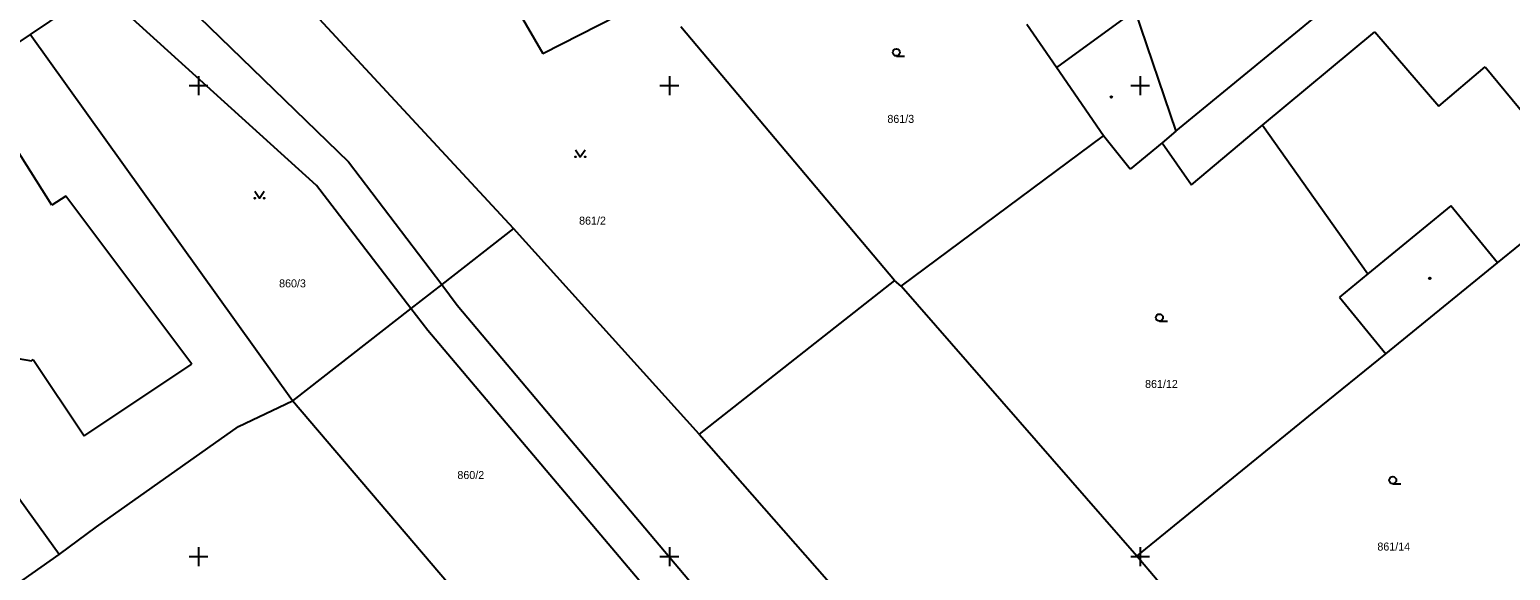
# Model space of a CAD drawing. Extents: x -711081 to -709338, y -1025122 to -1024092.
# Drawn here: x -710884 to -710805.3, y -1025025.7 to -1024997 of the extents above; entities that cross this region are included whole.
import ezdxf

# ---------------------------------------------------------------- set-up
doc = ezdxf.new("R2010")
doc.units = 0
for name, color, linetype in [('Z_hektometricka_sit', 7, 'Continuous'), ('Z_katastr_cisla_pozemkova', 7, 'Continuous'), ('Z_katastr_hranice', 7, 'Continuous'), ('Z_katastr_vnitrni_kresba', 7, 'Continuous'), ('Z_katastr_znacky_budov', 7, 'Continuous'), ('Z_katastr_znacky_kultur', 7, 'Continuous')]:
    doc.layers.add(name, color=color, linetype=linetype)

msp = doc.modelspace()

# ---------------------------------------------------------------- linework, layer by layer
at = {"layer": 'Z_hektometricka_sit'}
for p, q in [((-710875.5, -1025000), (-710874.5, -1025000)), ((-710875, -1024999.5), (-710875, -1025000.5)), ((-710850.5, -1025000), (-710849.5, -1025000)), ((-710850, -1024999.5), (-710850, -1025000.5)), ((-710825.5, -1025000), (-710824.5, -1025000)), ((-710825, -1024999.5), (-710825, -1025000.5)), ((-710875.5, -1025025), (-710874.5, -1025025)), ((-710875, -1025024.5), (-710875, -1025025.5)), ((-710850.5, -1025025), (-710849.5, -1025025)), ((-710850, -1025024.5), (-710850, -1025025.5)), ((-710825.5, -1025025), (-710824.5, -1025025)), ((-710825, -1025024.5), (-710825, -1025025.5))]:
    msp.add_line(p, q, dxfattribs=at)
at = {"layer": 'Z_katastr_hranice'}
for p, q in [((-710864.81, -1024984.43), (-710856.72, -1024998.29)), ((-710858.27, -1025007.58), (-710874.03, -1024990.6)), ((-710879.89, -1024994.55), (-710883.95, -1024997.28)), ((-710856.72, -1024998.29), (-710850.8, -1024995.28)), ((-710825.28, -1024996.01), (-710823.1, -1025002.42)), ((-710838.05, -1025010.34), (-710849.39, -1024996.89)), ((-710829.45, -1024999.04), (-710831.02, -1024996.76)), ((-710823.1, -1025002.42), (-710815.65, -1024996.32)), ((-710883.95, -1024997.28), (-710887.15, -1024999.45)), ((-710870.02, -1025016.74), (-710883.95, -1024997.28)), ((-710826.95, -1025002.67), (-710829.45, -1024999.04)), ((-710882.8, -1025006.35), (-710887.15, -1024999.45)), ((-710823.1, -1025002.42), (-710823.84, -1025003.03)), ((-710822.28, -1025005.26), (-710818.5, -1025002.1)), ((-710818.5, -1025002.1), (-710812.92, -1025010)), ((-710837.7, -1025010.65), (-710826.95, -1025002.67)), ((-710825.54, -1025004.43), (-710826.95, -1025002.67)), ((-710823.84, -1025003.03), (-710825.54, -1025004.43)), ((-710823.84, -1025003.03), (-710822.28, -1025005.26)), ((-710882.04, -1025005.87), (-710882.8, -1025006.35)), ((-710875.35, -1025014.79), (-710882.04, -1025005.87)), ((-710858.27, -1025007.58), (-710862.09, -1025010.56)), ((-710848.42, -1025018.5), (-710858.27, -1025007.58)), ((-710806.03, -1025009.41), (-710804.81, -1025008.42)), ((-710811.96, -1025014.24), (-710806.03, -1025009.41)), ((-710812.92, -1025010), (-710814.41, -1025011.23)), ((-710862.09, -1025010.56), (-710863.72, -1025011.83)), ((-710838.05, -1025010.34), (-710848.42, -1025018.5)), ((-710837.7, -1025010.65), (-710838.05, -1025010.34)), ((-710825.17, -1025024.98), (-710837.7, -1025010.65)), ((-710863.72, -1025011.83), (-710870.02, -1025016.74)), ((-710814.41, -1025011.23), (-710811.96, -1025014.24)), ((-710815.76, -1025017.32), (-710811.96, -1025014.24)), ((-710885.39, -1025014.35), (-710883.88, -1025014.61)), ((-710883.88, -1025014.61), (-710883.78, -1025014.53)), ((-710883.78, -1025014.53), (-710881.08, -1025018.59)), ((-710881.08, -1025018.59), (-710875.35, -1025014.79)), ((-710872.88, -1025018.09), (-710870.02, -1025016.74)), ((-710846.935, -1025043.764), (-710870.02, -1025016.74)), ((-710825.17, -1025024.98), (-710815.76, -1025017.32)), ((-710880.42, -1025023.42), (-710872.88, -1025018.09)), ((-710848.42, -1025018.5), (-710832.812, -1025036.252)), ((-710882.41, -1025024.89), (-710880.42, -1025023.42)), ((-710890.6, -1025030.64), (-710882.41, -1025024.89)), ((-710820.945, -1025029.939), (-710825.17, -1025024.98))]:
    msp.add_line(p, q, dxfattribs=at)
at = {"layer": 'Z_katastr_vnitrni_kresba'}
for p, q in [((-710876.91, -1024994.47), (-710867.04, -1025004.05)), ((-710868.74, -1025005.31), (-710879.08, -1024995.95)), ((-710825.28, -1024996.01), (-710829.45, -1024999.04)), ((-710818.5, -1025002.1), (-710812.54, -1024997.14)), ((-710812.54, -1024997.14), (-710809.15, -1025001.09)), ((-710809.15, -1025001.09), (-710806.68, -1024999.01)), ((-710806.68, -1024999.01), (-710804.58, -1025001.56)), ((-710867.04, -1025004.05), (-710862.09, -1025010.56)), ((-710863.72, -1025011.83), (-710868.74, -1025005.31)), ((-710808.5, -1025006.38), (-710812.92, -1025010)), ((-710806.03, -1025009.41), (-710808.5, -1025006.38)), ((-710862.09, -1025010.56), (-710861.26, -1025011.65)), ((-710862.83, -1025012.99), (-710863.72, -1025011.83)), ((-710861.26, -1025011.65), (-710840.03, -1025036.83)), ((-710841.51, -1025038.18), (-710862.83, -1025012.99)), ((-710882.41, -1025024.89), (-710884.81, -1025021.55))]:
    msp.add_line(p, q, dxfattribs=at)
at = {"layer": 'Z_katastr_znacky_budov'}
for centre in [(-710826.532, -1025000.61), (-710809.622, -1025010.23)]:
    msp.add_circle(centre, 0.0437, dxfattribs=at)
at = {"layer": 'Z_katastr_znacky_kultur'}
for p, q in [((-710837.948, -1024998.43), (-710837.511, -1024998.43)), ((-710823.978, -1025012.5), (-710823.541, -1025012.5)), ((-710811.588, -1025021.13), (-710811.151, -1025021.13))]:
    msp.add_line(p, q, dxfattribs=at)
for points in [[(-710854.98, -1025003.405), (-710854.73, -1025003.78), (-710854.48, -1025003.405)], [(-710872.02, -1025005.605), (-710871.77, -1025005.98), (-710871.52, -1025005.605)]]:
    msp.add_lwpolyline(points, dxfattribs=at)
for centre, radius in [((-710837.948, -1024998.242), 0.187), ((-710854.98, -1025003.78), 0.025), ((-710854.48, -1025003.78), 0.025), ((-710872.02, -1025005.98), 0.025), ((-710871.52, -1025005.98), 0.025), ((-710823.978, -1025012.312), 0.187), ((-710811.588, -1025020.942), 0.187)]:
    msp.add_circle(centre, radius, dxfattribs=at)

# ---------------------------------------------------------------- texts
at = {"layer": 'Z_katastr_cisla_pozemkova'}
for s, p in [('861/3', (-710838.424, -1025001.98)), ('861/2', (-710854.794, -1025007.38)), ('860/3', (-710870.723, -1025010.71)), ('861/12', (-710824.74, -1025016.049)), ('860/2', (-710861.256, -1025020.882)), ('861/14', (-710812.405, -1025024.679))]:
    msp.add_text(s, height=0.425, dxfattribs=at).set_placement(p)

doc.saveas('drawing.dxf')
